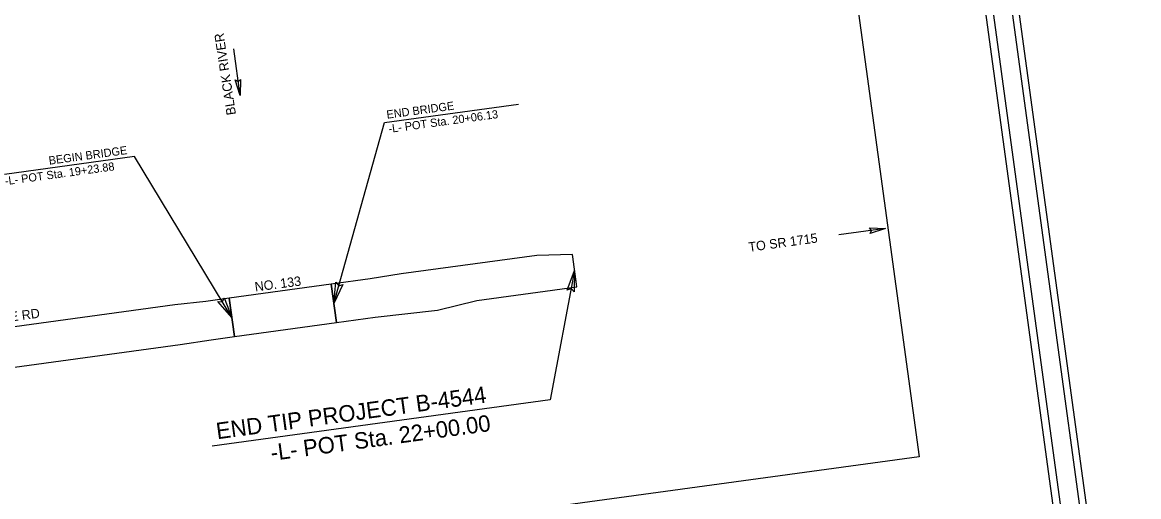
# Model space of a CAD drawing. Extents: x 2110583 to 2112764, y 580993 to 582575.
# Drawn here: x 2111873 to 2112764, y 581578 to 581957 of the extents above; entities that cross this region are included whole.
import ezdxf

# ---------------------------------------------------------------- set-up
doc = ezdxf.new("R2010")
doc.units = 0
for name, color, linetype in [('Default', 7, 'Continuous'), ('Prop DSN Text', 7, 'Continuous'), ('Prop Horizontal Alignment Station Label', 7, 'Continuous'), ('Prop Roadway Bridge', 7, 'Continuous'), ('Prop Shade Medium', 7, 'Continuous'), ('Prop Terminator CELL', 7, 'Continuous'), ('Sheet Plot Border Inside CELL', 7, 'Continuous'), ('Sheet Plot Border Outside CELL', 7, 'Continuous'), ('Sheet Title CELL', 7, 'Continuous')]:
    doc.layers.add(name, color=color, linetype=linetype)

msp = doc.modelspace()

# ---------------------------------------------------------------- linework, layer by layer
at = {"layer": 'Default'}
msp.add_lwpolyline([(2111026.43, 581851.1), (2112527.69, 582055.98), (2112588.53, 581610.11), (2111087.27, 581405.24)], close=True, dxfattribs=at)
at = {"layer": 'Prop DSN Text'}
for p, q in [((2112046.53, 581898.54), (2112041.48, 581935.55)), ((2112561.59, 581792.34), (2112524.57, 581787.29))]:
    msp.add_line(p, q, dxfattribs=at)
at = {"layer": 'Prop Horizontal Alignment Station Label'}
for p, q in [((2112161.9, 581876.9), (2112268.66, 581891.48)), ((2112121.43, 581732.57), (2112161.9, 581876.9)), ((2111962.26, 581849.66), (2111858.44, 581835.48)), ((2112039.93, 581721.45), (2111962.26, 581849.66)), ((2112313.52, 581758.79), (2112293.91, 581655.59)), ((2112293.91, 581655.59), (2112024.32, 581618.76))]:
    msp.add_line(p, q, dxfattribs=at)
at = {"layer": 'Prop Roadway Bridge'}
for p, q in [((2112119.24, 581747.84), (2112037.85, 581736.73)), ((2112123.41, 581717.29), (2112119.24, 581747.84)), ((2112037.85, 581736.73), (2112042.12, 581706.19)), ((2112042.12, 581706.19), (2112123.41, 581717.29))]:
    msp.add_line(p, q, dxfattribs=at)
at = {"layer": 'Prop Shade Medium'}
for p, q in [((2112283.51, 581770.84), (2112175, 581756.03)), ((2112311.76, 581771.67), (2112283.51, 581770.84)), ((2112312.03, 581769.69), (2112311.76, 581771.67)), ((2112315, 581747.89), (2112312.03, 581769.69)), ((2112150.31, 581752.08), (2112119.34, 581747.85)), ((2112175, 581756.03), (2112150.31, 581752.08)), ((2112119.34, 581747.85), (2112123.51, 581717.3)), ((2112235.39, 581735.01), (2112315.27, 581745.91)), ((2112315.27, 581745.91), (2112315, 581747.89)), ((2112019.27, 581734.19), (2111994.42, 581731.39)), ((2112037.85, 581736.73), (2112019.27, 581734.19)), ((2112042.02, 581706.18), (2112037.85, 581736.73)), ((2112204.15, 581727.29), (2112235.39, 581735.01)), ((2111994.42, 581731.39), (2111633.58, 581682.15)), ((2112154.47, 581721.53), (2112204.15, 581727.29)), ((2112123.51, 581717.3), (2112154.47, 581721.53)), ((2111644.95, 581651.4), (2111998.75, 581699.68)), ((2111998.75, 581699.68), (2112023.44, 581703.64)), ((2112023.44, 581703.64), (2112042.02, 581706.18))]:
    msp.add_line(p, q, dxfattribs=at)
at = {"layer": 'Prop Terminator CELL'}
for points in [[(2112046.98, 581911.32), (2112046.53, 581898.54), (2112042.6, 581910.8), (2112045.03, 581909.5)], [(2112548.8, 581792.79), (2112561.59, 581792.34), (2112549.33, 581788.41), (2112550.62, 581790.85)], [(2112307.63, 581743.03), (2112313.52, 581758.79), (2112313.32, 581741.86), (2112310.81, 581744.49)], [(2112128.65, 581747.77), (2112121.43, 581732.57), (2112123.09, 581749.42), (2112125.36, 581746.59)], [(2112033.78, 581737.11), (2112039.93, 581721.45), (2112028.77, 581734.19), (2112032.39, 581733.9)]]:
    msp.add_lwpolyline(points, close=True, dxfattribs=at)
at = {"layer": 'Sheet Plot Border Inside CELL'}
msp.add_lwpolyline([(2110773, 581021.72), (2112754.79, 581292.17), (2112583.51, 582547.28), (2110601.71, 582276.83)], close=True, dxfattribs=at)
at = {"layer": 'Sheet Plot Border Outside CELL'}
msp.add_lwpolyline([(2112585.22, 582574.72), (2110582.61, 582301.43), (2110761.18, 580992.92), (2112763.78, 581266.21)], close=True, dxfattribs=at)
at = {"layer": 'Sheet Title CELL'}
for points in [[(2112737.89, 581305.09), (2112570.68, 582530.32)], [(2112701.1, 581530.28), (2112565.55, 582523.58)]]:
    msp.add_lwpolyline(points, dxfattribs=at)

# ---------------------------------------------------------------- texts
at = {"layer": 'Prop DSN Text'}
for s, height, rotation, p in [('BLACK RIVER', 7.4721, 98.73252, (2112043.3, 581883.36)), ('TO SR 1715', 7.472, 7.77101, (2112452.87, 581773.74)), ('NO. 133', 7.472, 7.49037, (2112058.72, 581742.05)), ('-L- SR 1722 THREE BRIDGE RD ', 7.4721, 7.77101, (2111739.6, 581701.16))]:
    msp.add_text(s, height=height, rotation=rotation, dxfattribs=at).set_placement(p)
at = {"layer": 'Prop Horizontal Alignment Station Label'}
for s, height, p in [('END BRIDGE', 6.538, (2112163.87, 581879.88)), ('-L- POT Sta. 20+06.13', 6.5381, (2112165.42, 581868.55)), ('BEGIN BRIDGE', 6.5381, (2111894.24, 581843.19)), ('-L- POT Sta. 19+23.88', 6.5381, (2111859.24, 581826.86)), ('END TIP PROJECT B-4544', 13.1191, (2112028.32, 581624.15)), ('-L- POT Sta. 22+00.00', 13.1191, (2112071.78, 581606.91))]:
    msp.add_text(s, height=height, rotation=7.77798, dxfattribs=at).set_placement(p)

doc.saveas('drawing.dxf')
